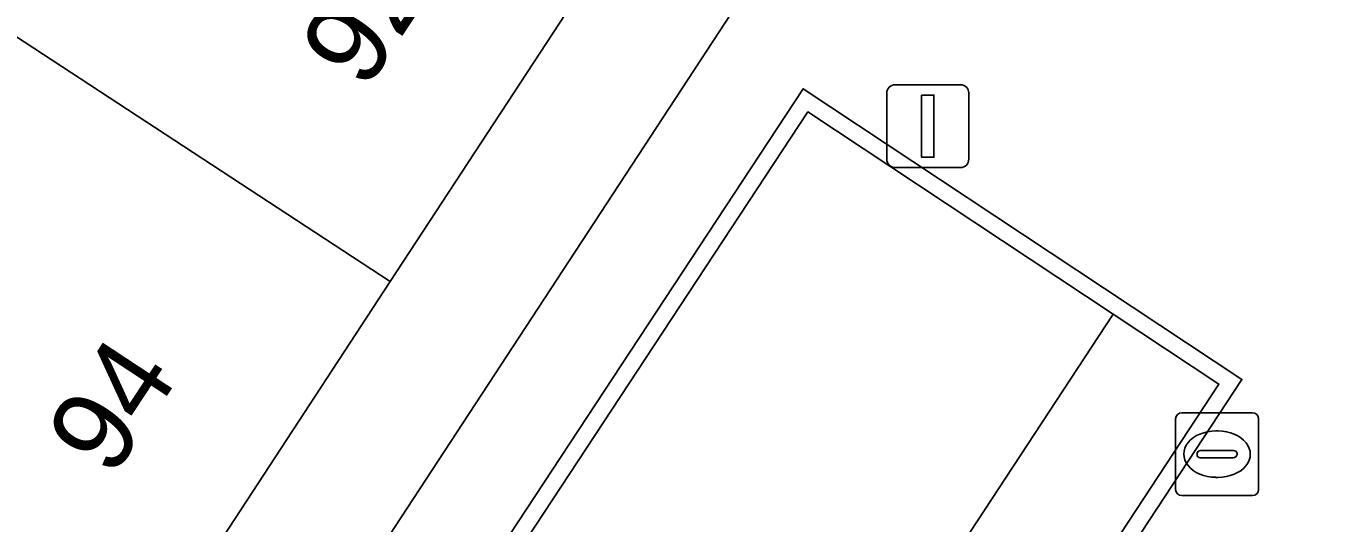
# Model space of a CAD drawing. Extents: x 155640 to 156811, y 382821 to 384049.
# Drawn here: x 156442.83 to 156458.45, y 383741.46 to 383747.46 of the extents above; entities that cross this region are included whole.
import ezdxf

# ---------------------------------------------------------------- set-up
doc = ezdxf.new("R2010")
doc.units = 0
for name, color, linetype in [('IMGEO_Brandkraan', 7, 'Continuous'), ('IMGEO_Lichtmast', 7, 'Continuous'), ('IMGEO_Lijnafwatering', 7, 'Continuous'), ('IMGEO_Muur', 7, 'Continuous'), ('IMGEO_Pand', 7, 'Continuous'), ('IMGEO_Pand_nummerreeks', 7, 'Continuous'), ('IMGEO_Rijbaan_lokaal_gesloten', 7, 'Continuous'), ('IMGEO_Voetgangersgebied_open', 7, 'Continuous'), ('IMGEO_Voetpad_gesloten', 7, 'Continuous')]:
    doc.layers.add(name, color=color, linetype=linetype)

msp = doc.modelspace()

# ---------------------------------------------------------------- linework, layer by layer
at = {"layer": 'IMGEO_Brandkraan'}
for p, q in [((156456.773, 383742.796), (156457.625, 383742.796)), ((156456.698, 383741.87), (156456.698, 383742.722)), ((156457.699, 383742.722), (156457.699, 383741.87)), ((156457.186, 383742.576), (156457.211, 383742.576)), ((156456.957, 383742.29), (156456.957, 383742.302)), ((156457, 383742.339), (156457.398, 383742.339)), ((156457.441, 383742.302), (156457.441, 383742.29)), ((156457.395, 383742.253), (156456.997, 383742.253)), ((156457.209, 383742.016), (156457.184, 383742.016)), ((156457.625, 383741.796), (156456.773, 383741.796))]:
    msp.add_line(p, q, dxfattribs=at)
for points in [[(156456.773, 383742.796), (156457.625, 383742.796)], [(156456.698, 383741.87), (156456.698, 383742.722)], [(156457.699, 383742.722), (156457.699, 383741.87)], [(156457.625, 383741.796), (156456.773, 383741.796)]]:
    msp.add_lwpolyline(points, dxfattribs=at)
for centre, radius, start, end in [((156456.775, 383742.72), 0.0765, 91.552, 178.448), ((156456.775, 383742.72), 0.0765, 91.552, 178.448), ((156457.623, 383742.72), 0.0765, 1.552, 88.448), ((156457.623, 383742.72), 0.0765, 1.552, 88.448), ((156456.997, 383742.299), 0.0403, 85.8775, 175.7526), ((156457.402, 383742.301), 0.0386, 1.7309, 96.639), ((156456.994, 383742.289), 0.0366, 178.938, 274.7102), ((156457.398, 383742.296), 0.043, 264.8664, 352.4533), ((156456.775, 383741.872), 0.0765, 181.552, 268.448), ((156456.775, 383741.872), 0.0765, 181.552, 268.448), ((156457.623, 383741.872), 0.0765, 271.552, 358.448), ((156457.623, 383741.872), 0.0765, 271.552, 358.448)]:
    msp.add_arc(centre, radius, start, end, dxfattribs=at)
for centre, major_axis, ratio, start_param, end_param in [((156457.185, 383742.296), (-0.387, 0.002), 0.722429, 4.712389, 7.853982), ((156457.21, 383742.296), (-0.39, 0.002), 0.717154, 1.570796, 4.712389)]:
    msp.add_ellipse(centre, major_axis=major_axis, ratio=ratio, start_param=start_param, end_param=end_param, dxfattribs=at)
at = {"layer": 'IMGEO_Lichtmast'}
for p, q in [((156453.314, 383746.755), (156454.104, 383746.755)), ((156454.104, 383746.755), (156453.314, 383746.755)), ((156453.214, 383745.855), (156453.214, 383746.655)), ((156453.214, 383746.655), (156453.214, 383745.855)), ((156454.204, 383746.655), (156454.204, 383745.855)), ((156454.204, 383745.855), (156454.204, 383746.655)), ((156454.104, 383745.755), (156453.314, 383745.755)), ((156453.314, 383745.755), (156454.104, 383745.755))]:
    msp.add_line(p, q, dxfattribs=at)
msp.add_lwpolyline([(156453.634, 383746.63), (156453.784, 383746.63), (156453.784, 383745.88), (156453.634, 383745.88), (156453.634, 383746.63)], dxfattribs=at)
for centre, start, end in [((156453.314, 383746.655), 90, 180), ((156453.314, 383746.655), 90, 180), ((156454.104, 383746.655), 0, 90), ((156454.104, 383746.655), 360, 90), ((156453.314, 383745.855), 180, 270), ((156453.314, 383745.855), 180, 270), ((156454.104, 383745.855), 270, 0), ((156454.104, 383745.855), 270, 0)]:
    msp.add_arc(centre, 0.1, start, end, dxfattribs=at)
at = {"layer": 'IMGEO_Lijnafwatering'}
for points in [[(156460.088, 383760.982), (156447.726, 383742.098)], [(156447.726, 383742.098), (156436.226, 383724.532)]]:
    msp.add_lwpolyline(points, dxfattribs=at)
at = {"layer": 'IMGEO_Muur'}
for points in [[(156457.498, 383743.199), (156452.207, 383746.705), (156444.177, 383734.498), (156449.505, 383731.026)], [(156457.222, 383743.142), (156452.661, 383736.197), (156449.447, 383731.302), (156444.454, 383734.556), (156452.264, 383746.427), (156455.946, 383743.987)]]:
    msp.add_lwpolyline(points, close=True, dxfattribs=at)
msp.add_lwpolyline([(156452.661, 383736.197), (156451.38, 383737.032), (156455.946, 383743.987)], dxfattribs=at)
at = {"layer": 'IMGEO_Pand'}
for points in [[(156439.113, 383756.204), (156436.129, 383751.648), (156447.225, 383744.38), (156450.206, 383748.938)], [(156436.129, 383751.648), (156433.145, 383747.093), (156444.244, 383739.822), (156447.225, 383744.38)]]:
    msp.add_lwpolyline(points, close=True, dxfattribs=at)
at = {"layer": 'IMGEO_Rijbaan_lokaal_gesloten'}
msp.add_lwpolyline([(156455.946, 383743.987), (156452.264, 383746.427), (156444.454, 383734.556), (156449.447, 383731.302), (156452.661, 383736.197), (156451.38, 383737.032)], close=True, dxfattribs=at)
at = {"layer": 'IMGEO_Voetgangersgebied_open'}
msp.add_lwpolyline([(156450.206, 383748.938), (156447.225, 383744.38), (156444.244, 383739.822), (156441.264, 383735.265), (156438.283, 383730.707), (156435.302, 383726.149), (156432.321, 383721.592), (156429.451, 383717.202), (156429.348, 383717.045), (156425.619, 383719.482), (156418.203, 383708.256), (156417.705, 383704.734), (156425.581, 383703.63), (156423.21, 383686.732)], dxfattribs=at)
msp.add_lwpolyline([(156449.505, 383731.026), (156444.177, 383734.498), (156452.207, 383746.705), (156457.498, 383743.199)], close=True, dxfattribs=at)
at = {"layer": 'IMGEO_Voetpad_gesloten'}
msp.add_lwpolyline([(156451.38, 383737.032), (156452.661, 383736.197), (156457.222, 383743.142), (156455.946, 383743.987)], close=True, dxfattribs=at)

# ---------------------------------------------------------------- texts
at = {"layer": 'IMGEO_Pand_nummerreeks'}
for s, p in [('92', (156446.925, 383746.667)), ('94', (156443.866, 383741.99))]:
    msp.add_text(s, height=1, rotation=56.6197, dxfattribs=at).set_placement(p)

doc.saveas('drawing.dxf')
